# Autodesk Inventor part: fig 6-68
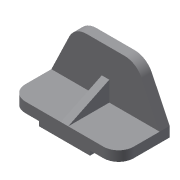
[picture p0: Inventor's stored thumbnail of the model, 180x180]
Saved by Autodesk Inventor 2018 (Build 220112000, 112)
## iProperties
Shininess: 77.0
Length Units: 11269
Angle Units: 11279
Time Units: 11290
Mass Units: 11283
Length Display Precision: 3
Angle Display Precision: 2
Created: 2001-12
Part Number: fig 6-68
Document SubType Name: Modeling
Designer: Renu Muthoo
Density: 1 g/cm^3
Material: Generic
Appearance: Default
Density: 0.0
Volumn: 0.0
Area: 0.0
PropertySet Name: Model Information
Control State: 0
Master: False
Checked Out: False
Author: Renu Muthoo
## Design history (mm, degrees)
node "Sketch1"
sketch "Sketch2"
  geometry: L1 (-67.219, 19.116)-(148.781, 19.116); L2 (148.781, 19.116)-(148.781, -0.884); L3 (-67.219, -0.884)-(-67.219, 19.116); L4 (-10.219, -0.884)-(-10.219, -9.884); L5 (-10.219, -9.884)-(91.781, -9.884); L6 (91.781, -9.884)-(91.781, -0.884); L7 (148.781, -0.884)-(91.781, -0.884); L8 (-10.219, -0.884)-(-67.219, -0.884)
  constraints: 16 end point, 5 parallel, 4 perpendicular, 2 equal length, 1 horizontal
  dimensions: "d0" = 102 distance of L4.end L5.end; "d1" = 57 distance of L4.start L3.start; "d2" = 29 distance between parallel lines of L1 L5; "d3" = 20 distance of L1.end L2.end
extrude "Extrusion1" new body sketch "Sketch2" distance "d4" = 102; taper "d5" = 0 deg
sketch "Sketch3"
  geometry: L1 (67.219, -19.116)-(-148.781, -19.116) reference; L2 (67.219, -19.116)-(31.475, -93.564); L3 (-2.781, -115.116)-(-78.781, -115.116); L4 (-113.038, -93.564)-(-148.781, -19.116); A1 r 38 centre (-2.781, -77.116) between (-2.781, -115.116) and (31.475, -93.564); A2 r 38 centre (-78.781, -77.116) between (-113.038, -93.564) and (-78.781, -115.116)
  constraints: 6 end point, 4 point on circle, 4 tangent, 2 centre point, 1 equal length, 1 equal radius, 1 parallel
  dimensions: "d6" = 96 distance between parallel lines of L3 L1; "d7" = 38 radius of A1; "d8" = 76 distance of A2.centre A1.centre
extrude "Extrusion2" join sketch "Sketch3" distance "d9" = 20; taper "d10" = 0 deg
fillet "Fillet1" dims "d11" = 30
workplane "Work Plane1"
sketch "Sketch7"
  geometry: L1 (0, -82)-(-39.557, 0)
  constraints: 2 end point
feature "Rib4" sketch "Sketch7" dims "d37" = 1, "d38" = 15, "d39" = 0
body "Solid1"
other parameters: "d12" = -108
